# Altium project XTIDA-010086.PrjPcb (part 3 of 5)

## Sheet XTIDA-010086_ADC.SchDoc
size 558 x 431 mm; Date: Not shown in title block; ApprovedBy: Not shown in title block; CheckedBy: Not shown in title block; Author: Not shown in title block; CompanyName: Not shown in title block; Engineer: Not shown in title block; Organization: Not shown in title block; Address1: Not shown in title block; Address2: Not shown in title block; Address3: Not shown in title block; Address4: Not shown in title block; DocumentNumber: 2; Revision: Use project parameter SCH_Rev; SheetNumber: 5; SheetTotal: 8; PageSetup: Record=PageOptions¦CenterHorizontal=True¦CenterVertical=True¦PrintScale=1.00¦XCorrection=1.00¦YCorrection=1.00¦PrintKind=0¦BorderSize=5000000¦LeftOffset=0¦BottomOffset=0¦Orientation=2¦PaperLength=1000¦PaperWidth=1000¦Scale=100¦PaperSource=15¦PrintQuality=600¦MediaType=1¦DitherType=10¦PaperKind=Letter¦PrintScaleMode=1
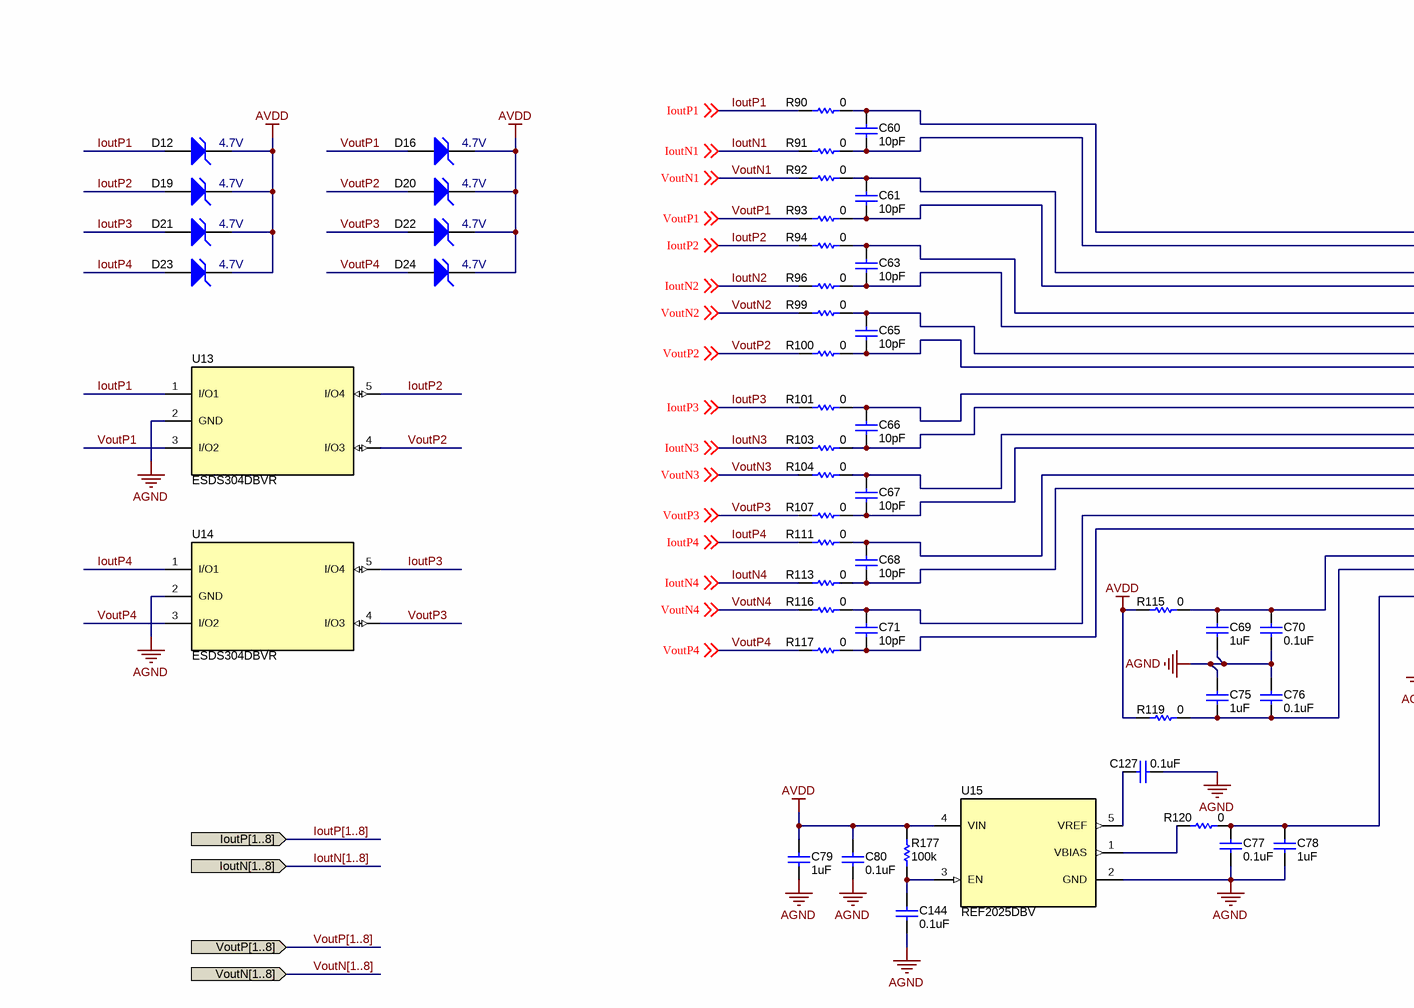
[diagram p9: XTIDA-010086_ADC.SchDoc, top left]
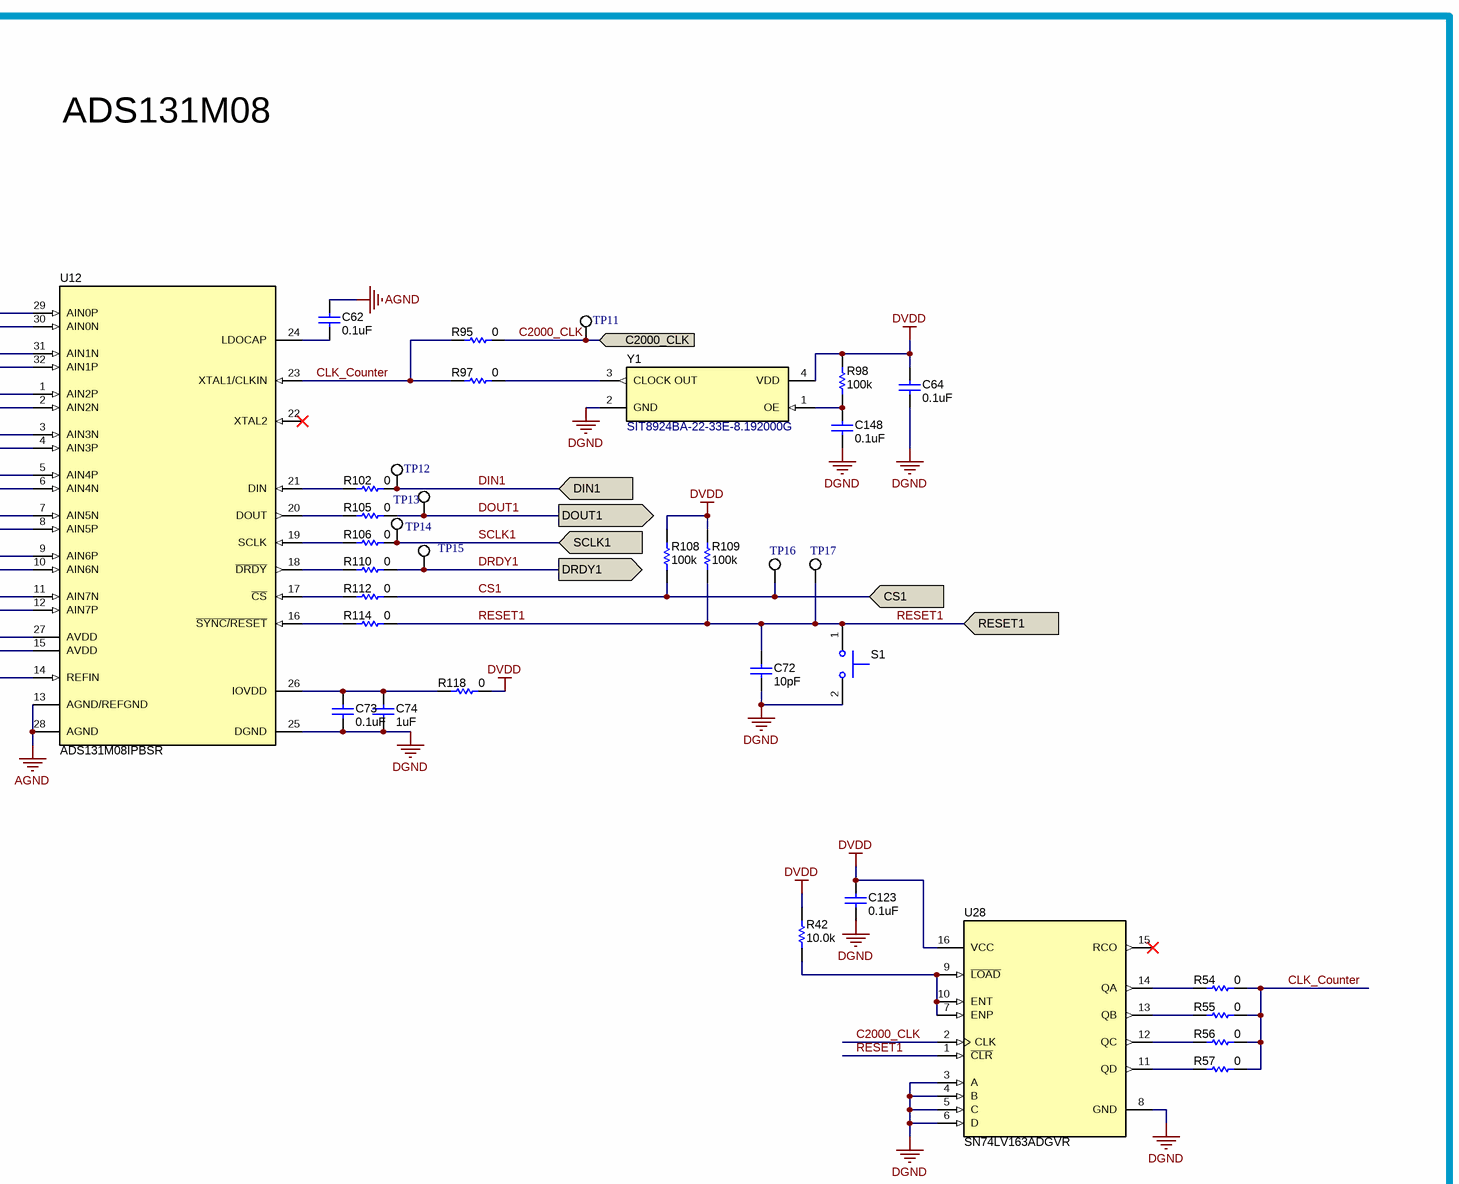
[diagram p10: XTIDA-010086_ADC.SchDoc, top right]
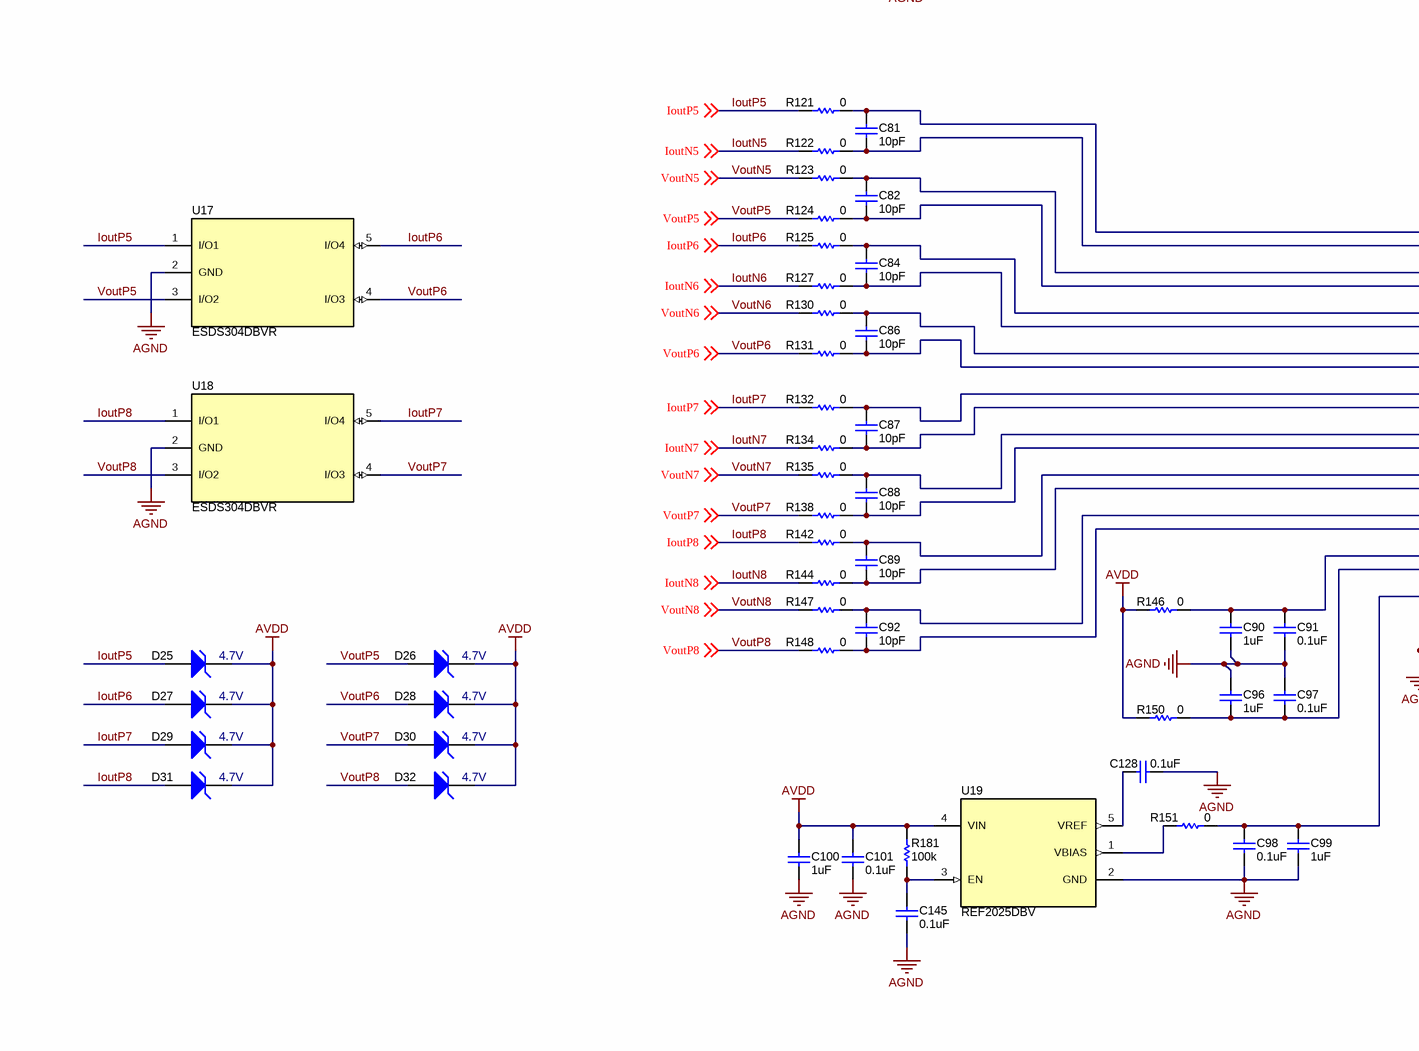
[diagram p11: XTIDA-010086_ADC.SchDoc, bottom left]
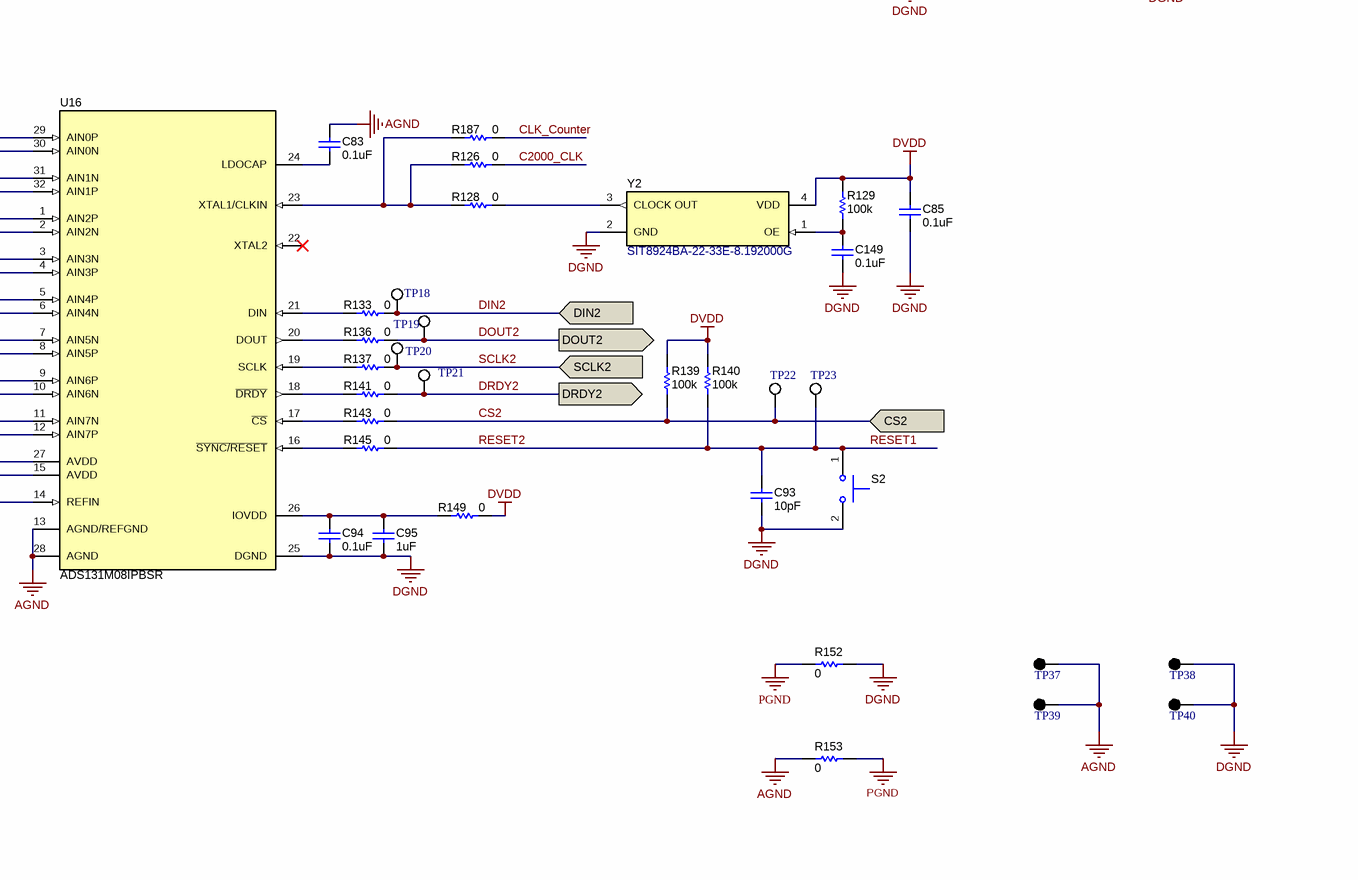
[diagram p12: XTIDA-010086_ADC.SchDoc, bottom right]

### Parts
C60  ValueDisplayed: 10pF  [0402]  (hidden comment: CGA2B2C0G1H100D050BA)
C61  ValueDisplayed: 10pF  [0402]  (hidden comment: CGA2B2C0G1H100D050BA)
C62  ValueDisplayed: 0.1uF  [0603]  (hidden comment: Capacitor)
C63  ValueDisplayed: 10pF  [0402]  (hidden comment: CGA2B2C0G1H100D050BA)
C64  ValueDisplayed: 0.1uF  [0603]  (hidden comment: Capacitor)
C65  ValueDisplayed: 10pF  [0402]  (hidden comment: CGA2B2C0G1H100D050BA)
C66  ValueDisplayed: 10pF  [0402]  (hidden comment: CGA2B2C0G1H100D050BA)
C67  ValueDisplayed: 10pF  [0402]  (hidden comment: CGA2B2C0G1H100D050BA)
C68  ValueDisplayed: 10pF  [0402]  (hidden comment: CGA2B2C0G1H100D050BA)
C69  ValueDisplayed: 1uF  [0603]  (hidden comment: Capacitor)
C70  ValueDisplayed: 0.1uF  [0603]  (hidden comment: Capacitor)
C71  ValueDisplayed: 10pF  [0402]  (hidden comment: CGA2B2C0G1H100D050BA)
C72  ValueDisplayed: 10pF  [0603]  (hidden comment: Capacitor)
C73  ValueDisplayed: 0.1uF  [0603]  (hidden comment: Capacitor)
C74  ValueDisplayed: 1uF  [0603]  (hidden comment: Capacitor)
C75  ValueDisplayed: 1uF  [0603]  (hidden comment: Capacitor)
C76  ValueDisplayed: 0.1uF  [0603]  (hidden comment: Capacitor)
C77  ValueDisplayed: 0.1uF  [0603]  (hidden comment: Capacitor)
C78  ValueDisplayed: 1uF  [0603]  (hidden comment: Capacitor)
C79  ValueDisplayed: 1uF  [0603]  (hidden comment: Capacitor)
C80  ValueDisplayed: 0.1uF  [0603]  (hidden comment: Capacitor)
C81  ValueDisplayed: 10pF  [0402]  (hidden comment: CGA2B2C0G1H100D050BA)
C82  ValueDisplayed: 10pF  [0402]  (hidden comment: CGA2B2C0G1H100D050BA)
C83  ValueDisplayed: 0.1uF  [0603]  (hidden comment: Capacitor)
C84  ValueDisplayed: 10pF  [0402]  (hidden comment: CGA2B2C0G1H100D050BA)
C85  ValueDisplayed: 0.1uF  [0603]  (hidden comment: Capacitor)
C86  ValueDisplayed: 10pF  [0402]  (hidden comment: CGA2B2C0G1H100D050BA)
C87  ValueDisplayed: 10pF  [0402]  (hidden comment: CGA2B2C0G1H100D050BA)
C88  ValueDisplayed: 10pF  [0402]  (hidden comment: CGA2B2C0G1H100D050BA)
C89  ValueDisplayed: 10pF  [0402]  (hidden comment: CGA2B2C0G1H100D050BA)
C90  ValueDisplayed: 1uF  [0603]  (hidden comment: Capacitor)
C91  ValueDisplayed: 0.1uF  [0603]  (hidden comment: Capacitor)
C92  ValueDisplayed: 10pF  [0402]  (hidden comment: CGA2B2C0G1H100D050BA)
C93  ValueDisplayed: 10pF  [0603]  (hidden comment: Capacitor)
C94  ValueDisplayed: 0.1uF  [0603]  (hidden comment: Capacitor)
C95  ValueDisplayed: 1uF  [0603]  (hidden comment: Capacitor)
C96  ValueDisplayed: 1uF  [0603]  (hidden comment: Capacitor)
C97  ValueDisplayed: 0.1uF  [0603]  (hidden comment: Capacitor)
C98  ValueDisplayed: 0.1uF  [0603]  (hidden comment: Capacitor)
C99  ValueDisplayed: 1uF  [0603]  (hidden comment: Capacitor)
C100  ValueDisplayed: 1uF  [0603]  (hidden comment: Capacitor)
C101  ValueDisplayed: 0.1uF  [0603]  (hidden comment: Capacitor)
C123  ValueDisplayed: 0.1uF  [0603]  (hidden comment: Capacitor)
C127  ValueDisplayed: 0.1uF  [0603]  (hidden comment: Capacitor)
C128  ValueDisplayed: 0.1uF  [0603]  (hidden comment: Capacitor)
C144  ValueDisplayed: 0.1uF  [0603]  (hidden comment: Capacitor)
C145  ValueDisplayed: 0.1uF  [0603]  (hidden comment: Capacitor)
C148  ValueDisplayed: 0.1uF  [0603]  (hidden comment: Capacitor)
C149  ValueDisplayed: 0.1uF  [0603]  (hidden comment: Capacitor)
D12  value 4.7V  [SOD-123]  (hidden comment: MMSZ5230B-7-F)
D16  value 4.7V  [SOD-123]  (hidden comment: MMSZ5230B-7-F)
D19  value 4.7V  [SOD-123]  (hidden comment: MMSZ5230B-7-F)
D20  value 4.7V  [SOD-123]  (hidden comment: MMSZ5230B-7-F)
D21  value 4.7V  [SOD-123]  (hidden comment: MMSZ5230B-7-F)
D22  value 4.7V  [SOD-123]  (hidden comment: MMSZ5230B-7-F)
D23  value 4.7V  [SOD-123]  (hidden comment: MMSZ5230B-7-F)
D24  value 4.7V  [SOD-123]  (hidden comment: MMSZ5230B-7-F)
D25  value 4.7V  [SOD-123]  (hidden comment: MMSZ5230B-7-F)
D26  value 4.7V  [SOD-123]  (hidden comment: MMSZ5230B-7-F)
D27  value 4.7V  [SOD-123]  (hidden comment: MMSZ5230B-7-F)
D28  value 4.7V  [SOD-123]  (hidden comment: MMSZ5230B-7-F)
D29  value 4.7V  [SOD-123]  (hidden comment: MMSZ5230B-7-F)
D30  value 4.7V  [SOD-123]  (hidden comment: MMSZ5230B-7-F)
D31  value 4.7V  [SOD-123]  (hidden comment: MMSZ5230B-7-F)
D32  value 4.7V  [SOD-123]  (hidden comment: MMSZ5230B-7-F)
R42  ValueDisplayed: 10.0k  [0402]  (hidden comment: CRCW040210K0FKED)
R54  ValueDisplayed: 0  [0402]  (hidden comment: CRCW04020000Z0ED)
R55  ValueDisplayed: 0  [0402]  (hidden comment: CRCW04020000Z0ED)
R56  ValueDisplayed: 0  [0402]  (hidden comment: CRCW04020000Z0ED)
R57  ValueDisplayed: 0  [0402]  (hidden comment: CRCW04020000Z0ED)
R90  ValueDisplayed: 0  [0402]  (hidden comment: CRCW04020000Z0ED)
R91  ValueDisplayed: 0  [0402]  (hidden comment: CRCW04020000Z0ED)
R92  ValueDisplayed: 0  [0402]  (hidden comment: CRCW04020000Z0ED)
R93  ValueDisplayed: 0  [0402]  (hidden comment: CRCW04020000Z0ED)
R94  ValueDisplayed: 0  [0402]  (hidden comment: CRCW04020000Z0ED)
R95  ValueDisplayed: 0  [0402]  (hidden comment: CRCW04020000Z0ED)
R96  ValueDisplayed: 0  [0402]  (hidden comment: CRCW04020000Z0ED)
R97  ValueDisplayed: 0  [0402]  (hidden comment: CRCW04020000Z0ED)
R98  ValueDisplayed: 100k  [0603]  (hidden comment: RC0603FR-07100KL)
R99  ValueDisplayed: 0  [0402]  (hidden comment: CRCW04020000Z0ED)
R100  ValueDisplayed: 0  [0402]  (hidden comment: CRCW04020000Z0ED)
R101  ValueDisplayed: 0  [0402]  (hidden comment: CRCW04020000Z0ED)
R102  ValueDisplayed: 0  [0402]  (hidden comment: CRCW04020000Z0ED)
R103  ValueDisplayed: 0  [0402]  (hidden comment: CRCW04020000Z0ED)
R104  ValueDisplayed: 0  [0402]  (hidden comment: CRCW04020000Z0ED)
R105  ValueDisplayed: 0  [0402]  (hidden comment: CRCW04020000Z0ED)
R106  ValueDisplayed: 0  [0402]  (hidden comment: CRCW04020000Z0ED)
R107  ValueDisplayed: 0  [0402]  (hidden comment: CRCW04020000Z0ED)
R108  ValueDisplayed: 100k  [0603]  (hidden comment: RC0603FR-07100KL)
R109  ValueDisplayed: 100k  [0603]  (hidden comment: RC0603FR-07100KL)
R110  ValueDisplayed: 0  [0402]  (hidden comment: CRCW04020000Z0ED)
R111  ValueDisplayed: 0  [0402]  (hidden comment: CRCW04020000Z0ED)
R112  ValueDisplayed: 0  [0402]  (hidden comment: CRCW04020000Z0ED)
R113  ValueDisplayed: 0  [0402]  (hidden comment: CRCW04020000Z0ED)
R114  ValueDisplayed: 0  [0402]  (hidden comment: CRCW04020000Z0ED)
R115  ValueDisplayed: 0  [0402]  (hidden comment: CRCW04020000Z0ED)
R116  ValueDisplayed: 0  [0402]  (hidden comment: CRCW04020000Z0ED)
R117  ValueDisplayed: 0  [0402]  (hidden comment: CRCW04020000Z0ED)
R118  ValueDisplayed: 0  [0402]  (hidden comment: CRCW04020000Z0ED)
R119  ValueDisplayed: 0  [0402]  (hidden comment: CRCW04020000Z0ED)
R120  ValueDisplayed: 0  [0402]  (hidden comment: CRCW04020000Z0ED)
R121  ValueDisplayed: 0  [0402]  (hidden comment: CRCW04020000Z0ED)
R122  ValueDisplayed: 0  [0402]  (hidden comment: CRCW04020000Z0ED)
R123  ValueDisplayed: 0  [0402]  (hidden comment: CRCW04020000Z0ED)
R124  ValueDisplayed: 0  [0402]  (hidden comment: CRCW04020000Z0ED)
R125  ValueDisplayed: 0  [0402]  (hidden comment: CRCW04020000Z0ED)
R126  ValueDisplayed: 0  [0402]  (hidden comment: CRCW04020000Z0ED)
R127  ValueDisplayed: 0  [0402]  (hidden comment: CRCW04020000Z0ED)
R128  ValueDisplayed: 0  [0402]  (hidden comment: CRCW04020000Z0ED)
R129  ValueDisplayed: 100k  [0603]  (hidden comment: RC0603FR-07100KL)
R130  ValueDisplayed: 0  [0402]  (hidden comment: CRCW04020000Z0ED)
R131  ValueDisplayed: 0  [0402]  (hidden comment: CRCW04020000Z0ED)
R132  ValueDisplayed: 0  [0402]  (hidden comment: CRCW04020000Z0ED)
R133  ValueDisplayed: 0  [0402]  (hidden comment: CRCW04020000Z0ED)
R134  ValueDisplayed: 0  [0402]  (hidden comment: CRCW04020000Z0ED)
R135  ValueDisplayed: 0  [0402]  (hidden comment: CRCW04020000Z0ED)
R136  ValueDisplayed: 0  [0402]  (hidden comment: CRCW04020000Z0ED)
R137  ValueDisplayed: 0  [0402]  (hidden comment: CRCW04020000Z0ED)
R138  ValueDisplayed: 0  [0402]  (hidden comment: CRCW04020000Z0ED)
R139  ValueDisplayed: 100k  [0603]  (hidden comment: RC0603FR-07100KL)
R140  ValueDisplayed: 100k  [0603]  (hidden comment: RC0603FR-07100KL)
R141  ValueDisplayed: 0  [0402]  (hidden comment: CRCW04020000Z0ED)
R142  ValueDisplayed: 0  [0402]  (hidden comment: CRCW04020000Z0ED)
R143  ValueDisplayed: 0  [0402]  (hidden comment: CRCW04020000Z0ED)
R144  ValueDisplayed: 0  [0402]  (hidden comment: CRCW04020000Z0ED)
R145  ValueDisplayed: 0  [0402]  (hidden comment: CRCW04020000Z0ED)
R146  ValueDisplayed: 0  [0402]  (hidden comment: CRCW04020000Z0ED)
R147  ValueDisplayed: 0  [0402]  (hidden comment: CRCW04020000Z0ED)
R148  ValueDisplayed: 0  [0402]  (hidden comment: CRCW04020000Z0ED)
R149  ValueDisplayed: 0  [0402]  (hidden comment: CRCW04020000Z0ED)
R150  ValueDisplayed: 0  [0402]  (hidden comment: CRCW04020000Z0ED)
R151  ValueDisplayed: 0  [0402]  (hidden comment: CRCW04020000Z0ED)
R152  ValueDisplayed: 0  [5108]  (hidden comment: 5108)
R153  ValueDisplayed: 0  [5108]  (hidden comment: 5108)
R177  ValueDisplayed: 100k  [0603]  (hidden comment: RC0603FR-07100KL)
R181  ValueDisplayed: 100k  [0603]  (hidden comment: RC0603FR-07100KL)
R187  ValueDisplayed: 0  [0402]  (hidden comment: CRCW04020000Z0ED)
S1  Switch_PushButton  [SW_TL1015AF160QG]  (value not drawn)
S2  Switch_PushButton  [SW_TL1015AF160QG]  (value not drawn)
TP11  5002  [Keystone5002]  (value not drawn)
TP12  5002  [Keystone5002]  (value not drawn)
TP13  5002  [Keystone5002]  (value not drawn)
TP14  5002  [Keystone5002]  (value not drawn)
TP15  5002  [Keystone5002]  (value not drawn)
TP16  5002  [Keystone5002]  (value not drawn)
TP17  5002  [Keystone5002]  (value not drawn)
TP18  5002  [Keystone5002]  (value not drawn)
TP19  5002  [Keystone5002]  (value not drawn)
TP20  5002  [Keystone5002]  (value not drawn)
TP21  5002  [Keystone5002]  (value not drawn)
TP22  5002  [Keystone5002]  (value not drawn)
TP23  5002  [Keystone5002]  (value not drawn)
TP37  5001  [Keystone5001]  (value not drawn)
TP38  5001  [Keystone5001]  (value not drawn)
TP39  5001  [Keystone5001]  (value not drawn)
TP40  5001  [Keystone5001]  (value not drawn)
U12  ADS131M08IPBSR  [PBS0032A_N]
U13  ESDS304DBVR  [DBV0005A_N]
U14  ESDS304DBVR  [DBV0005A_N]
U15  REF2025DBV  [DBV0005A_N]
U16  ADS131M08IPBSR  [PBS0032A_N]
U17  ESDS304DBVR  [DBV0005A_N]
U18  ESDS304DBVR  [DBV0005A_N]
U19  REF2025DBV  [DBV0005A_N]
U28  SN74LV163ADGVR  [DGV0016A_L]
Y1  SIT8924BA-22-33E-8.192000G  [SiTime_SiT8924B_2]
Y2  SIT8924BA-22-33E-8.192000G  [SiTime_SiT8924B_2]

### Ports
C2000_CLK (in), CS1 (in), CS2 (in), DIN1 (in), DIN2 (in), DOUT1 (out), DOUT2 (out), DRDY1 (out), DRDY2 (out), IoutN[1..8] (in), IoutP[1..8] (in), RESET1 (in), SCLK1 (in), SCLK2 (in), VoutN[1..8] (in), VoutP[1..8] (in)

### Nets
AGND: C62.1 C69.2 C70.2 C75.1 C76.1 C77.2 C78.2 C79.2 C80.2 C83.1 C90.2 C91.2 C96.1 C97.1 C98.2 C99.2 C100.2 C101.2 C127.1 C128.1 C144.2 C145.2 R153.1 TP37.1 TP39.1 U12.13(AGND/REFGND) U12.28(AGND) U13.2(GND) U14.2(GND) U15.2(GND) U16.13(AGND/REFGND) U16.28(AGND) U17.2(GND) U18.2(GND) U19.2(GND)
AVDD: C79.1 C80.1 C100.1 C101.1 D12.1(K) D16.1(K) D19.1(K) D20.1(K) D21.1(K) D22.1(K) D23.1(K) D24.1(K) D25.1(K) D26.1(K) D27.1(K) D28.1(K) D29.1(K) D30.1(K) D31.1(K) D32.1(K) R115.1 R119.1 R146.1 R150.1 R177.2 R181.2 U15.4(VIN) U19.4(VIN)
DGND: C64.2 C72.1 C73.2 C74.2 C85.2 C93.1 C94.2 C95.2 C123.2 C148.2 C149.2 R152.2 S1.2 S2.2 TP38.1 TP40.1 U12.25(DGND) U16.25(DGND) U28.3(A) U28.4(B) U28.5(C) U28.6(D) U28.8(GND) Y1.2(GND) Y2.2(GND)
DVDD: C64.1 C85.1 C123.1 R42.2 R98.2 R108.2 R109.2 R118.2 R129.2 R139.2 R140.2 R149.2 U28.16(VCC) Y1.4(VDD) Y2.4(VDD)
PGND: R152.1 R153.2
C2000_CLK: R95.2 R126.2 TP11.1 U28.2(CLK) ; port C2000_CLK
CLK_Counter: R54.2 R55.2 R56.2 R57.2 R95.1 R97.1 R187.2 U12.23(XTAL1/CLKIN)
CS1: R108.1 R112.2 TP16.1 ; port CS1
CS2: R139.1 R143.2 TP22.1 ; port CS2
DIN1: R102.2 TP12.1 ; port DIN1
DIN2: R133.2 TP18.1 ; port DIN2
DOUT1: R105.2 TP13.1 ; port DOUT1
DOUT2: R136.2 TP19.1 ; port DOUT2
DRDY1: R110.2 TP15.1 ; port DRDY1
DRDY2: R141.2 TP21.1 ; port DRDY2
IoutN1: R91.1 ; off-sheet IoutN1
IoutN2: R96.1 ; off-sheet IoutN2
IoutN3: R103.1 ; off-sheet IoutN3
IoutN4: R113.1 ; off-sheet IoutN4
IoutN5: R122.1 ; off-sheet IoutN5
IoutN6: R127.1 ; off-sheet IoutN6
IoutN7: R134.1 ; off-sheet IoutN7
IoutN8: R144.1 ; off-sheet IoutN8
IoutP1: D12.2(A) R90.1 U13.1(I/O1) ; off-sheet IoutP1
IoutP2: D19.2(A) R94.1 U13.5(I/O4) ; off-sheet IoutP2
IoutP3: D21.2(A) R101.1 U14.5(I/O4) ; off-sheet IoutP3
IoutP4: D23.2(A) R111.1 U14.1(I/O1) ; off-sheet IoutP4
IoutP5: D25.2(A) R121.1 U17.1(I/O1) ; off-sheet IoutP5
IoutP6: D27.2(A) R125.1 U17.5(I/O4) ; off-sheet IoutP6
IoutP7: D29.2(A) R132.1 U18.5(I/O4) ; off-sheet IoutP7
IoutP8: D31.2(A) R142.1 U18.1(I/O1) ; off-sheet IoutP8
RESET1: C72.2 C93.2 R109.1 R114.2 R140.1 R145.2 S1.1 S2.1 TP17.1 TP23.1 U28.1(~{CLR}) ; port RESET1  [also labelled RESET2]
SCLK1: R106.2 TP14.1 ; port SCLK1
SCLK2: R137.2 TP20.1 ; port SCLK2
VoutN1: R92.1 ; off-sheet VoutN1
VoutN2: R99.1 ; off-sheet VoutN2
VoutN3: R104.1 ; off-sheet VoutN3
VoutN4: R116.1 ; off-sheet VoutN4
VoutN5: R123.1 ; off-sheet VoutN5
VoutN6: R130.1 ; off-sheet VoutN6
VoutN7: R135.1 ; off-sheet VoutN7
VoutN8: R147.1 ; off-sheet VoutN8
VoutP1: D16.2(A) R93.1 U13.3(I/O2) ; off-sheet VoutP1
VoutP2: D20.2(A) R100.1 U13.4(I/O3) ; off-sheet VoutP2
VoutP3: D22.2(A) R107.1 U14.4(I/O3) ; off-sheet VoutP3
VoutP4: D24.2(A) R117.1 U14.3(I/O2) ; off-sheet VoutP4
VoutP5: D26.2(A) R124.1 U17.3(I/O2) ; off-sheet VoutP5
VoutP6: D28.2(A) R131.1 U17.4(I/O3) ; off-sheet VoutP6
VoutP7: D30.2(A) R138.1 U18.4(I/O3) ; off-sheet VoutP7
VoutP8: D32.2(A) R148.1 U18.3(I/O2) ; off-sheet VoutP8
NetC60_1: C60.1 R90.2 U12.29(AIN0P)
NetC60_2: C60.2 R91.2 U12.30(AIN0N)
NetC61_1: C61.1 R92.2 U12.31(AIN1N)
NetC61_2: C61.2 R93.2 U12.32(AIN1P)
NetC62_2: C62.2 U12.24(LDOCAP)
NetC63_1: C63.1 R94.2 U12.1(AIN2P)
NetC63_2: C63.2 R96.2 U12.2(AIN2N)
NetC65_1: C65.1 R99.2 U12.3(AIN3N)
NetC65_2: C65.2 R100.2 U12.4(AIN3P)
NetC66_1: C66.1 R101.2 U12.5(AIN4P)
NetC66_2: C66.2 R103.2 U12.6(AIN4N)
NetC67_1: C67.1 R104.2 U12.7(AIN5N)
NetC67_2: C67.2 R107.2 U12.8(AIN5P)
NetC68_1: C68.1 R111.2 U12.9(AIN6P)
NetC68_2: C68.2 R113.2 U12.10(AIN6N)
NetC69_1: C69.1 C70.1 R115.2 U12.27(AVDD)
NetC71_1: C71.1 R116.2 U12.11(AIN7N)
NetC71_2: C71.2 R117.2 U12.12(AIN7P)
NetC73_1: C73.1 C74.1 R118.1 U12.26(IOVDD)
NetC75_2: C75.2 C76.2 R119.2 U12.15(AVDD)
NetC77_1: C77.1 C78.1 R120.2 U12.14(REFIN)
NetC81_1: C81.1 R121.2 U16.29(AIN0P)
NetC81_2: C81.2 R122.2 U16.30(AIN0N)
NetC82_1: C82.1 R123.2 U16.31(AIN1N)
NetC82_2: C82.2 R124.2 U16.32(AIN1P)
NetC83_2: C83.2 U16.24(LDOCAP)
NetC84_1: C84.1 R125.2 U16.1(AIN2P)
NetC84_2: C84.2 R127.2 U16.2(AIN2N)
NetC86_1: C86.1 R130.2 U16.3(AIN3N)
NetC86_2: C86.2 R131.2 U16.4(AIN3P)
NetC87_1: C87.1 R132.2 U16.5(AIN4P)
NetC87_2: C87.2 R134.2 U16.6(AIN4N)
NetC88_1: C88.1 R135.2 U16.7(AIN5N)
NetC88_2: C88.2 R138.2 U16.8(AIN5P)
NetC89_1: C89.1 R142.2 U16.9(AIN6P)
NetC89_2: C89.2 R144.2 U16.10(AIN6N)
NetC90_1: C90.1 C91.1 R146.2 U16.27(AVDD)
NetC92_1: C92.1 R147.2 U16.11(AIN7N)
NetC92_2: C92.2 R148.2 U16.12(AIN7P)
NetC94_1: C94.1 C95.1 R149.1 U16.26(IOVDD)
NetC96_2: C96.2 C97.2 R150.2 U16.15(AVDD)
NetC98_1: C98.1 C99.1 R151.2 U16.14(REFIN)
NetC127_2: C127.2 U15.5(VREF)
NetC128_2: C128.2 U19.5(VREF)
NetC144_1: C144.1 R177.1 U15.3(EN)
NetC145_1: C145.1 R181.1 U19.3(EN)
NetC148_1: C148.1 R98.1 Y1.1(OE)
NetC149_1: C149.1 R129.1 Y2.1(OE)
NetR42_1: R42.1 U28.7(ENP) U28.9(~{LOAD}) U28.10(ENT)
NetR54_1: R54.1 U28.14(QA)
NetR55_1: R55.1 U28.13(QB)
NetR56_1: R56.1 U28.12(QC)
NetR57_1: R57.1 U28.11(QD)
NetR97_2: R97.2 Y1.3(CLOCK_OUT)
NetR102_1: R102.1 U12.21(DIN)
NetR105_1: R105.1 U12.20(DOUT)
NetR106_1: R106.1 U12.19(SCLK)
NetR110_1: R110.1 U12.18(~{DRDY})
NetR112_1: R112.1 U12.17(~{CS})
NetR114_1: R114.1 U12.16(~{SYNC/RESET})
NetR120_1: R120.1 U15.1(VBIAS)
NetR126_1: R126.1 R128.1 R187.1 U16.23(XTAL1/CLKIN)
NetR128_2: R128.2 Y2.3(CLOCK_OUT)
NetR133_1: R133.1 U16.21(DIN)
NetR136_1: R136.1 U16.20(DOUT)
NetR137_1: R137.1 U16.19(SCLK)
NetR141_1: R141.1 U16.18(~{DRDY})
NetR143_1: R143.1 U16.17(~{CS})
NetR145_1: R145.1 U16.16(~{SYNC/RESET})
NetR151_1: R151.1 U19.1(VBIAS)

Not connected (* = marked no-connect by the designer): U12 22(XTAL2)*; U16 22(XTAL2)*; U28 15(RCO)*

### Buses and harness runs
bus IoutN[1..8] = port IoutN[1..8]
bus IoutP[1..8] = port IoutP[1..8]
bus VoutN[1..8] = port VoutN[1..8]
bus VoutP[1..8] = port VoutP[1..8]

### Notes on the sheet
- ADS131M08

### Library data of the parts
C60 C61 C63 C65-C68 C71 C81 C82 C84 C86-C89 C92 = CGA2B2C0G1H100D050BA: CAP, CERM, 10 pF, 50 V,+/- 5%, C0G/NP0, AEC-Q200 Grade 1, 0402; Manufacturer: TDK; Polarized: N; CompType: Capacitor; Value: 10pF; U/M: EA; Cap_F: 0.00000000001; Tolerance_%: 5; VDC_V: 50; Value2: 50V; TaMin_C: -55; TaMax_C: 125; SizeArea_mm2: 0.5; SizeAreaWB_mm2: 3; SizeX_mm: 1; SizeZ_mm: 0.6; AEC Category: Q200; AEC Qualified: Y
C62 C64 C70 C73 C76 C77 C80 C83 C85 C91 C94 C97 C98 C101 C123 C127 C128 C144 C145 C148 C149 = CMP-0006752-5: CAP, CERM, 0.1 uF, 25 V, +/- 5%, X7R, 0603; PartNumber: 06033C104JAT2A; Manufacturer: AVX; Polarized: N; Value: 0.1uF; U/M: EA; Cap_F: 100nF; ESR_ohm: 0.05; Value1: 0.05 ohm; VDC_V: 25V; TaMin_C: -55°C; TaMax_C: 125°C; AEC Category: Q200; SizeArea_mm2: 1.28; SizeAreaWB_mm2: 4.68; SizeX_mm: 1.6; SizeY_mm: 0.8; SizeZ_mm: 1
C69 C74 C75 C78 C79 C90 C95 C96 C99 C100 = CMP-0007405-4: CAP, CERM, 1 uF, 25 V, +/- 10%, X7R, 0603; PartNumber: GRM188R71E105KA12D; Manufacturer: MuRata; Polarized: N; Value: 1uF; U/M: EA; Cap_F: 1µF; Value1: Unknown; VDC_V: 25V; TaMin_C: -55°C; TaMax_C: 125°C; AEC Category: Q200; SizeArea_mm2: 1.28; SizeAreaWB_mm2: 4.68; SizeX_mm: 1.6; SizeY_mm: 0.8; SizeZ_mm: 1
C72 C93 = CMP-0006761-4: CAP, CERM, 10 pF, 50 V, +/- 5%, C0G/NP0, 0603; PartNumber: 06035A100JAT2A; Manufacturer: AVX; Polarized: N; Value: 10pF; U/M: EA; ESR_ohm: 4.03d; Value1: 0.403 ohm; VDC_V: 50V; TaMin_C: -55°C; TaMax_C: 125°C; AEC Category: Q200; SizeArea_mm2: 1.28; SizeAreaWB_mm2: 4.68; SizeX_mm: 1.6; SizeY_mm: 0.8; SizeZ_mm: 1
D12 D16 D19-D32 = CMP-0005801-3: Diode, Zener, 4.7 V, 500 mW, SOD-123; Manufacturer: Diodes Inc.; SizeArea_mm2: 6.545; AEC Category: Q101; SizeAreaWB_mm2: 13.095; RJA_CperW: 350; SizeX_mm: 3.85; Value1: 0.5W; SizeY_mm: 1.7; SizeZ_mm: 1.35; Power_W: 500mW
R42 = CRCW040210K0FKED: RES, 10.0 k, 1%, 0.063 W, 0402; Manufacturer: Vishay-Dale; CompType: Resistor; Value: 10.0k; Res_ohm: 10000; Value_Code: 10k0; Tolerance_%: 1; Power_W: 0.063; Value2: 0.063W; VDC_V: 50; TempCo: 100 ppm/C; SizeArea_mm2: 0.5; SizeZ_mm: 0.6; EIA_Code: E96; U/M: EA; AEC Category: Q200; Green_Lifecycle: Active; Green_REACh: Passed
R54-R57 R90-R97 R99-R107 R110-R128 R130-R138 R141-R151 R187 = CRCW04020000Z0ED: RES, 0, 5%, 0.063 W, 0402; Manufacturer: Vishay-Dale; CompType: Resistor; Value: 0; Value_Code: 0000; Tolerance_%: 5; Power_W: 0.063; Value2: 0.063W; VDC_V: 50; TempCo: 200 ppm/C; SizeArea_mm2: 0.5; SizeX_mm: 1; SizeZ_mm: 0.6; EIA_Code: E24; U/M: EA; AEC Category: Q200; Green_Lifecycle: Active; Green_REACh: Passed
R98 R108 R109 R129 R139 R140 R177 R181 = CMP-0022735-5: RES, 100 k, 1%, 0.1 W, 0603; Manufacturer: Yageo; Power_W: 100mW; TempCo: 100 ppm/C; Value: 100k; EIA_Code: E96; SizeX_mm: 1.6; SizeY_mm: 0.8; SizeZ_mm: 1; Value2: 0.1W; SizeArea_mm2: 1.28; AEC Qualified: N; VDC_V: 75V; AEC Category: Q200; SizeAreaWB_mm2: 4.68
R152 R153 = 5108: RES, 0, 1%, 0.5 W, 1206; Manufacturer: Keystone; CompType: Resistor; Value: 0; Tolerance_%: 1; Power_W: 0.5; Value2: 0.5W; TempCo: ppm/C; SizeArea_mm2: 5.185; SizeX_mm: 3.05; SizeY_mm: 1.7; SizeZ_mm: 0.84; U/M: EA; AEC Category: Q200; AEC Qualified: N
S1 S2 = CMP-0002143-3: Switch, Tactile, SPST-NO, 0.05A, 12V, SMT; PartNumber: TL1015AF160QG; Manufacturer: E-Switch; SwitchFunction: Off-Mom; PositionCount: 1; CurrentRating_mA: 50A
TP11-TP23 = 5002: Test Point, Miniature, White, TH; Manufacturer: Keystone; CompType: Test Point Loop; ContactFinish: Silver; Green_Lifecycle: Active; Green_REACh: Passed
TP37-TP40 = 5001: Test Point, Miniature, Black, TH; Manufacturer: Keystone; CompType: Test Point Loop; ContactFinish: Silver; Green_Lifecycle: Active; Green_REACh: Passed
U12 U16 = CMP-0085527-1: 8-Channel, 24-Bit, Simultaneously-Sampling, Delta-Sigma ADC, PBS0032A (TQFP-32); Manufacturer: Texas Instruments; SizeZ_mm: 1.2; SizeArea_mm2: 49; SizeAreaWB_mm2: 81; AEC Category: Q200; AEC Qualified: N; SizeY_mm: 7; CompType: IC
U13 U14 U17 U18 = CMP-0085633-1: 3.6V Data-Line Surge and 30kV ESD Protection Diode Array, DBV0005A (SOT-23-5); Manufacturer: Texas Instruments; AEC Category: Q200; SizeX_mm: 2.8; SizeY_mm: 2.9; CompType: IC; Rating: Catalog; SizeZ_mm: 1.45; AEC Qualified: N; SizeAreaWB_mm2: 14.82; SizeArea_mm2: 8.12
U15 U19 = CMP-0013048-2: DUAL OUTPUT VOLTAGE REFERENCE 2.5V, DBV0005A (SOT-5); Manufacturer: Texas Instruments; SizeX_mm: 2.8; SizeY_mm: 2.9; CompType: IC; SizeZ_mm: 1.45; SizeArea_mm2: 8.12; SizeAreaWB_mm2: 14.82; U/M: EA
U28 = CMP-0076579-1: 4-BIT SYNCHRONOUS BINARY COUNTER, DGV0016A (TVSOP-16); Manufacturer: Texas Instruments; SizeAreaWB_mm2: 70.56; SizeArea_mm2: 40.96; SizeZ_mm: 1.2; SizeY_mm: 6.4; U/M: EA; CompType: IC
Y1 Y2 = CMP-0081928-1: Oscillator, 8.192 MHz, 15 pF, AEC-Q200 Grade 1, SMD; Manufacturer: SiTime; TaMin_C: -40°C; Frequency Stability: 25 ppm; SizeAreaWB_mm2: 14.7; Load Capacitance: 15 pF; TaMax_C: 125°C; SizeZ_mm: 0.8; SizeX_mm: 2.5; SizeY_mm: 3.2; SizeArea_mm2: 8; AEC Qualified: Y; AEC Grade: 1; AEC Category: Q200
